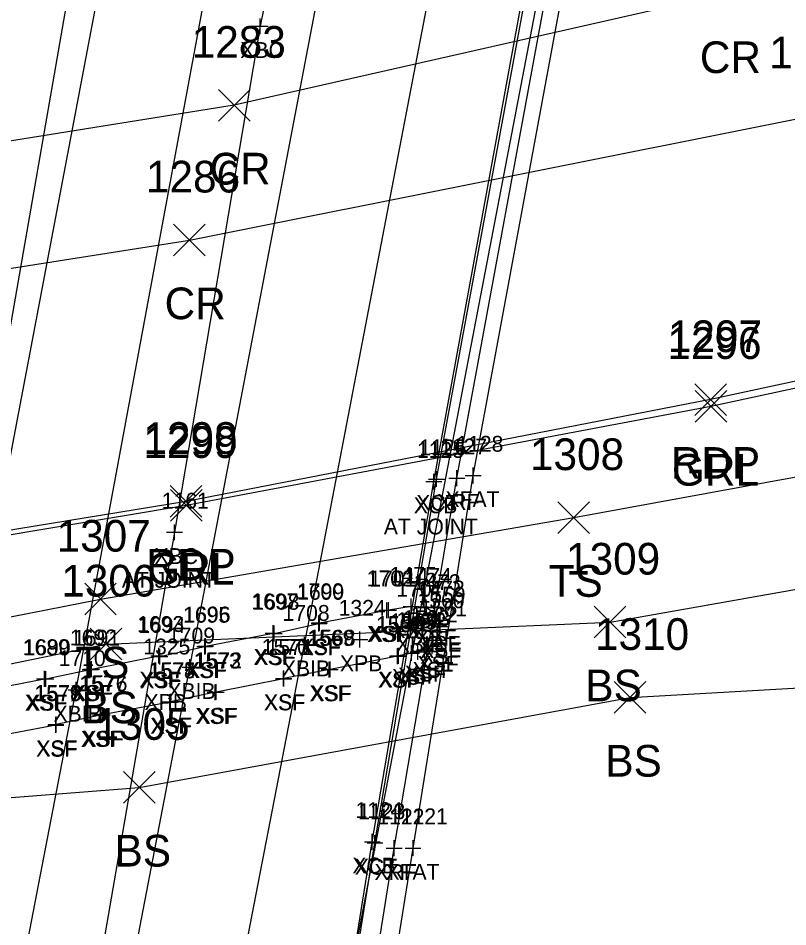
# Model space of a CAD drawing. Extents: x 1683147 to 1683637, y 416837 to 418211.
# Drawn here: x 1683231.5 to 1683280.1, y 417486.5 to 417543.9 of the extents above; entities that cross this region are included whole.
import ezdxf

# ---------------------------------------------------------------- set-up
doc = ezdxf.new("R2010")
doc.units = 0
for name, color, linetype in [('B_A', 7, 'Continuous'), ('B_C', 7, 'Continuous'), ('B_I', 7, 'Continuous'), ('B_TIC', 7, 'Continuous'), ('BB', 7, 'Continuous'), ('BDC', 7, 'Continuous'), ('BDEFAULT', 7, 'Continuous'), ('BELB', 7, 'Continuous'), ('BF', 7, 'Continuous'), ('BR', 7, 'Continuous'), ('L_A', 7, 'Continuous'), ('L_I', 7, 'Continuous'), ('L_TIC', 7, 'Continuous'), ('LELB', 7, 'Continuous'), ('P_A', 7, 'Continuous'), ('P_I', 7, 'Continuous'), ('P_TIC', 7, 'Continuous'), ('PET', 7, 'Continuous'), ('PRC', 7, 'Continuous'), ('R_A', 7, 'Continuous'), ('R_I', 7, 'Continuous'), ('R_TIC', 7, 'Continuous'), ('RGR', 7, 'Continuous')]:
    doc.layers.add(name, color=color, linetype=linetype)

msp = doc.modelspace()

# ---------------------------------------------------------------- linework, layer by layer
at = {"layer": 'B_TIC'}
for p, q in [((1683246.826, 417543.339), (1683246.901, 417543.339)), ((1683257.956, 417514.755), (1683258.031, 417514.755)), ((1683259.241, 417514.807), (1683259.316, 417514.807)), ((1683260.268, 417514.98), (1683260.344, 417514.98)), ((1683257.786, 417514.592), (1683257.862, 417514.592)), ((1683241.403, 417511.39), (1683241.478, 417511.39)), ((1683256.344, 417506.709), (1683256.42, 417506.709)), ((1683254.811, 417506.467), (1683254.886, 417506.467)), ((1683254.931, 417506.48), (1683255.006, 417506.48)), ((1683254.931, 417506.48), (1683255.006, 417506.48)), ((1683257.294, 417506.646), (1683257.369, 417506.646)), ((1683257.856, 417506.241), (1683257.931, 417506.241)), ((1683250.529, 417505.632), (1683250.604, 417505.632)), ((1683250.56, 417505.669), (1683250.636, 417505.669)), ((1683256.809, 417505.82), (1683256.885, 417505.82)), ((1683258.112, 417505.846), (1683258.187, 417505.846)), ((1683258.112, 417505.846), (1683258.187, 417505.846)), ((1683247.629, 417505.03), (1683247.705, 417505.03)), ((1683247.695, 417505.003), (1683247.771, 417505.003)), ((1683258.166, 417505.451), (1683258.241, 417505.451)), ((1683258.166, 417505.1), (1683258.242, 417505.1)), ((1683253.12, 417504.62), (1683253.195, 417504.62)), ((1683257.993, 417504.582), (1683258.068, 417504.582)), ((1683243.311, 417504.185), (1683243.386, 417504.185)), ((1683243.368, 417504.201), (1683243.443, 417504.201)), ((1683249.615, 417504.3), (1683249.691, 417504.3)), ((1683256.782, 417503.841), (1683256.858, 417503.841)), ((1683257.195, 417503.97), (1683257.271, 417503.97)), ((1683257.687, 417504.197), (1683257.762, 417504.197)), ((1683240.415, 417503.599), (1683240.491, 417503.599)), ((1683240.479, 417503.544), (1683240.555, 417503.544)), ((1683255.494, 417503.576), (1683255.57, 417503.576)), ((1683255.551, 417503.597), (1683255.626, 417503.597)), ((1683256.385, 417503.769), (1683256.46, 417503.769)), ((1683236.077, 417502.727), (1683236.152, 417502.727)), ((1683236.164, 417502.751), (1683236.239, 417502.751)), ((1683242.378, 417502.873), (1683242.454, 417502.873)), ((1683251.173, 417502.72), (1683251.248, 417502.72)), ((1683251.237, 417502.737), (1683251.312, 417502.737)), ((1683233.19, 417502.135), (1683233.266, 417502.135)), ((1683233.277, 417502.131), (1683233.352, 417502.131)), ((1683240.776, 417502.18), (1683240.851, 417502.18)), ((1683248.285, 417502.147), (1683248.361, 417502.147)), ((1683248.307, 417502.161), (1683248.382, 417502.161)), ((1683235.189, 417501.44), (1683235.264, 417501.44)), ((1683243.965, 417501.289), (1683244.041, 417501.289)), ((1683244.039, 417501.308), (1683244.115, 417501.308)), ((1683241.107, 417500.671), (1683241.182, 417500.671)), ((1683241.153, 417500.687), (1683241.229, 417500.687)), ((1683236.731, 417499.843), (1683236.806, 417499.843)), ((1683236.831, 417499.86), (1683236.907, 417499.86)), ((1683233.903, 417499.221), (1683233.978, 417499.221)), ((1683233.923, 417499.26), (1683233.998, 417499.26)), ((1683253.899, 417491.851), (1683253.975, 417491.851)), ((1683254.069, 417491.776), (1683254.144, 417491.776)), ((1683255.282, 417491.444), (1683255.357, 417491.444)), ((1683256.474, 417491.459), (1683256.549, 417491.459))]:
    msp.add_line(p, q, dxfattribs=at)
for points in [[(1683246.822, 417542.839), (1683246.822, 417543.839)], [(1683246.322, 417543.339), (1683247.322, 417543.339)], [(1683259.237, 417514.307), (1683259.237, 417515.307)], [(1683260.265, 417514.48), (1683260.265, 417515.48)], [(1683257.452, 417514.755), (1683258.452, 417514.755)], [(1683257.783, 417514.092), (1683257.783, 417515.092)], [(1683257.952, 417514.255), (1683257.952, 417515.255)], [(1683258.737, 417514.807), (1683259.737, 417514.807)], [(1683259.765, 417514.98), (1683260.765, 417514.98)], [(1683257.283, 417514.592), (1683258.283, 417514.592)], [(1683241.399, 417510.89), (1683241.399, 417511.89)], [(1683240.899, 417511.39), (1683241.899, 417511.39)], [(1683254.807, 417505.967), (1683254.807, 417506.967)], [(1683254.927, 417505.98), (1683254.927, 417506.98)], [(1683254.927, 417505.98), (1683254.927, 417506.98)], [(1683255.841, 417506.709), (1683256.841, 417506.709)], [(1683256.341, 417506.209), (1683256.341, 417507.209)], [(1683257.29, 417506.146), (1683257.29, 417507.146)], [(1683257.852, 417505.741), (1683257.852, 417506.741)], [(1683250.525, 417505.132), (1683250.525, 417506.132)], [(1683250.557, 417505.169), (1683250.557, 417506.169)], [(1683254.307, 417506.467), (1683255.307, 417506.467)], [(1683254.427, 417506.48), (1683255.427, 417506.48)], [(1683254.427, 417506.48), (1683255.427, 417506.48)], [(1683256.79, 417506.646), (1683257.79, 417506.646)], [(1683256.806, 417505.32), (1683256.806, 417506.32)], [(1683257.352, 417506.241), (1683258.352, 417506.241)], [(1683258.108, 417505.346), (1683258.108, 417506.346)], [(1683258.108, 417505.346), (1683258.108, 417506.346)], [(1683247.626, 417504.53), (1683247.626, 417505.53)], [(1683250.025, 417505.632), (1683251.025, 417505.632)], [(1683250.057, 417505.669), (1683251.057, 417505.669)], [(1683256.306, 417505.82), (1683257.306, 417505.82)], [(1683257.608, 417505.846), (1683258.608, 417505.846)], [(1683257.608, 417505.846), (1683258.608, 417505.846)], [(1683258.162, 417504.951), (1683258.162, 417505.951)], [(1683258.163, 417504.6), (1683258.163, 417505.6)], [(1683247.126, 417505.03), (1683248.126, 417505.03)], [(1683247.192, 417505.003), (1683248.192, 417505.003)], [(1683247.692, 417504.503), (1683247.692, 417505.503)], [(1683253.116, 417504.12), (1683253.116, 417505.12)], [(1683257.662, 417505.451), (1683258.662, 417505.451)], [(1683257.663, 417505.1), (1683258.663, 417505.1)], [(1683257.989, 417504.082), (1683257.989, 417505.082)], [(1683243.307, 417503.685), (1683243.307, 417504.685)], [(1683243.364, 417503.701), (1683243.364, 417504.701)], [(1683249.612, 417503.8), (1683249.612, 417504.8)], [(1683252.616, 417504.62), (1683253.616, 417504.62)], [(1683257.192, 417503.47), (1683257.192, 417504.47)], [(1683257.489, 417504.582), (1683258.489, 417504.582)], [(1683257.683, 417503.697), (1683257.683, 417504.697)], [(1683240.412, 417503.099), (1683240.412, 417504.099)], [(1683240.476, 417503.044), (1683240.476, 417504.044)], [(1683242.807, 417504.185), (1683243.807, 417504.185)], [(1683242.864, 417504.201), (1683243.864, 417504.201)], [(1683249.112, 417504.3), (1683250.112, 417504.3)], [(1683255.491, 417503.076), (1683255.491, 417504.076)], [(1683255.547, 417503.097), (1683255.547, 417504.097)], [(1683256.279, 417503.841), (1683257.279, 417503.841)], [(1683256.381, 417503.269), (1683256.381, 417504.269)], [(1683256.692, 417503.97), (1683257.692, 417503.97)], [(1683256.779, 417503.341), (1683256.779, 417504.341)], [(1683257.183, 417504.197), (1683258.183, 417504.197)], [(1683236.073, 417502.227), (1683236.073, 417503.227)], [(1683236.16, 417502.251), (1683236.16, 417503.251)], [(1683239.912, 417503.599), (1683240.912, 417503.599)], [(1683239.976, 417503.544), (1683240.976, 417503.544)], [(1683242.375, 417502.373), (1683242.375, 417503.373)], [(1683251.169, 417502.22), (1683251.169, 417503.22)], [(1683251.233, 417502.237), (1683251.233, 417503.237)], [(1683254.991, 417503.576), (1683255.991, 417503.576)], [(1683255.047, 417503.597), (1683256.047, 417503.597)], [(1683255.881, 417503.769), (1683256.881, 417503.769)], [(1683235.573, 417502.727), (1683236.573, 417502.727)], [(1683235.66, 417502.751), (1683236.66, 417502.751)], [(1683240.772, 417501.68), (1683240.772, 417502.68)], [(1683241.875, 417502.873), (1683242.875, 417502.873)], [(1683248.282, 417501.647), (1683248.282, 417502.647)], [(1683248.303, 417501.661), (1683248.303, 417502.661)], [(1683250.669, 417502.72), (1683251.669, 417502.72)], [(1683250.733, 417502.737), (1683251.733, 417502.737)], [(1683232.687, 417502.135), (1683233.687, 417502.135)], [(1683232.773, 417502.131), (1683233.773, 417502.131)], [(1683233.187, 417501.635), (1683233.187, 417502.635)], [(1683233.273, 417501.631), (1683233.273, 417502.631)], [(1683240.272, 417502.18), (1683241.272, 417502.18)], [(1683247.782, 417502.147), (1683248.782, 417502.147)], [(1683247.803, 417502.161), (1683248.803, 417502.161)], [(1683235.185, 417500.94), (1683235.185, 417501.94)], [(1683243.962, 417500.789), (1683243.962, 417501.789)], [(1683244.036, 417500.808), (1683244.036, 417501.808)], [(1683234.685, 417501.44), (1683235.685, 417501.44)], [(1683241.103, 417500.171), (1683241.103, 417501.171)], [(1683241.15, 417500.187), (1683241.15, 417501.187)], [(1683243.462, 417501.289), (1683244.462, 417501.289)], [(1683243.536, 417501.308), (1683244.536, 417501.308)], [(1683236.828, 417499.36), (1683236.828, 417500.36)], [(1683240.603, 417500.671), (1683241.603, 417500.671)], [(1683240.65, 417500.687), (1683241.65, 417500.687)], [(1683236.227, 417499.843), (1683237.227, 417499.843)], [(1683236.328, 417499.86), (1683237.328, 417499.86)], [(1683236.727, 417499.343), (1683236.727, 417500.343)], [(1683233.399, 417499.221), (1683234.399, 417499.221)], [(1683233.419, 417499.26), (1683234.419, 417499.26)], [(1683233.899, 417498.721), (1683233.899, 417499.721)], [(1683233.919, 417498.76), (1683233.919, 417499.76)], [(1683253.896, 417491.351), (1683253.896, 417492.351)], [(1683253.396, 417491.851), (1683254.396, 417491.851)], [(1683253.565, 417491.776), (1683254.565, 417491.776)], [(1683254.065, 417491.276), (1683254.065, 417492.276)], [(1683255.278, 417490.944), (1683255.278, 417491.944)], [(1683256.47, 417490.959), (1683256.47, 417491.959)], [(1683254.778, 417491.444), (1683255.778, 417491.444)], [(1683255.97, 417491.459), (1683256.97, 417491.459)]]:
    msp.add_lwpolyline(points, dxfattribs=at)
at = {"layer": 'BB'}
for points in [[(1683247.534, 417457.283), (1683256.806, 417505.82), (1683275.504, 417603.185), (1683284.507, 417651.57)], [(1683240.224, 417455.825), (1683249.612, 417504.3), (1683268.309, 417601.755), (1683277.362, 417650.167)], [(1683233.056, 417454.423), (1683242.375, 417502.873), (1683260.963, 417600.277), (1683270.09, 417648.672)], [(1683225.817, 417452.979), (1683235.185, 417501.44), (1683252.981, 417597.315), (1683262.91, 417647.271)], [(1683218.639, 417451.571), (1683227.942, 417499.995), (1683246.282, 417596.559), (1683255.565, 417645.821)]]:
    msp.add_lwpolyline(points, dxfattribs=at)
at = {"layer": 'BDC'}
for points in [[(1683248.051, 417455.436), (1683253.896, 417491.851), (1683257.783, 417514.592), (1683265.936, 417559.114), (1683272.886, 417593.685), (1683281.07, 417631.095), (1683286.315, 417653.984)], [(1683248.206, 417455.394), (1683254.065, 417491.776), (1683257.952, 417514.755), (1683266.138, 417559.151), (1683273.116, 417593.593), (1683281.173, 417630.923), (1683286.527, 417654.075)]]:
    msp.add_lwpolyline(points, dxfattribs=at)
at = {"layer": 'BDEFAULT'}
for points in [[(1683258.108, 417505.846), (1683257.852, 417506.241), (1683257.29, 417506.646), (1683256.341, 417506.709), (1683254.927, 417506.48)], [(1683228.937, 417501.313), (1683233.187, 417502.135), (1683233.273, 417502.131), (1683236.073, 417502.727), (1683236.16, 417502.751), (1683240.412, 417503.599), (1683240.476, 417503.544), (1683243.307, 417504.185), (1683243.364, 417504.201), (1683247.626, 417505.03), (1683247.692, 417505.003), (1683250.525, 417505.632), (1683250.557, 417505.669), (1683254.807, 417506.467), (1683254.927, 417506.48)], [(1683258.108, 417505.846), (1683258.162, 417505.451), (1683258.163, 417505.1), (1683257.989, 417504.582), (1683257.683, 417504.197), (1683257.192, 417503.97), (1683256.779, 417503.841), (1683256.381, 417503.769), (1683255.547, 417503.597), (1683255.491, 417503.576), (1683251.233, 417502.737), (1683251.169, 417502.72), (1683248.303, 417502.161), (1683248.282, 417502.147), (1683244.036, 417501.308), (1683243.962, 417501.289), (1683241.15, 417500.687), (1683241.103, 417500.671), (1683236.828, 417499.86), (1683236.727, 417499.843), (1683233.919, 417499.26), (1683233.899, 417499.221), (1683229.649, 417498.419)]]:
    msp.add_lwpolyline(points, dxfattribs=at)
at = {"layer": 'BELB'}
for points in [[(1683269.206, 417650.948), (1683260.393, 417611.397), (1683256.447, 417590.785), (1683246.822, 417543.339), (1683241.399, 417511.39), (1683234.932, 417474.067), (1683231.661, 417452.147)], [(1683255.821, 417648.166), (1683248.035, 417613.702), (1683243.06, 417587.805), (1683234.781, 417546.02), (1683228.274, 417508.761), (1683222.317, 417473.758), (1683218.863, 417449.537)]]:
    msp.add_lwpolyline(points, dxfattribs=at)
at = {"layer": 'BF'}
msp.add_lwpolyline([(1683250.624, 417454.9), (1683256.47, 417491.459), (1683260.265, 417514.98), (1683268.347, 417558.692), (1683275.679, 417593.916), (1683283.544, 417630.285), (1683288.924, 417653.565)], dxfattribs=at)
at = {"layer": 'BR'}
msp.add_lwpolyline([(1683248.519, 417448.641), (1683249.479, 417455.186), (1683255.278, 417491.444), (1683259.237, 417514.807), (1683267.406, 417559.099), (1683274.406, 417593.753), (1683282.508, 417630.53), (1683290.526, 417665.488)], dxfattribs=at)
at = {"layer": 'L_TIC'}
for points in [[(1683265.627, 417511.319), (1683267.627, 417513.319)], [(1683267.627, 417511.319), (1683265.627, 417513.319)], [(1683235.725, 417506.171), (1683237.725, 417508.171)], [(1683237.725, 417506.171), (1683235.725, 417508.171)], [(1683267.914, 417504.721), (1683269.914, 417506.721)], [(1683269.914, 417504.721), (1683267.914, 417506.721)], [(1683236.075, 417503.337), (1683238.075, 417505.337)], [(1683238.075, 417503.337), (1683236.075, 417505.337)], [(1683269.177, 417499.965), (1683271.177, 417501.965)], [(1683271.177, 417499.965), (1683269.177, 417501.965)], [(1683238.174, 417494.288), (1683240.174, 417496.288)], [(1683240.174, 417494.288), (1683238.174, 417496.288)]]:
    msp.add_lwpolyline(points, dxfattribs=at)
at = {"layer": 'LELB'}
for points in [[(1683205.058, 417500.966), (1683236.725, 417507.171), (1683266.627, 417512.319), (1683295.742, 417517.653), (1683322.975, 417523.071), (1683351.626, 417530.069)], [(1683205.591, 417497.875), (1683237.075, 417504.337), (1683268.914, 417505.721), (1683296.171, 417510.545), (1683323.546, 417516.347), (1683350.433, 417523.399)], [(1683205.213, 417492.626), (1683239.174, 417495.288), (1683270.177, 417500.965), (1683298.559, 417502.586), (1683327.653, 417507.076), (1683349.696, 417514.294)]]:
    msp.add_lwpolyline(points, dxfattribs=at)
at = {"layer": 'P_TIC'}
for points in [[(1683244.179, 417537.35), (1683246.179, 417539.35)], [(1683246.179, 417537.35), (1683244.179, 417539.35)], [(1683241.343, 417528.845), (1683243.343, 417530.845)], [(1683243.343, 417528.845), (1683241.343, 417530.845)], [(1683274.263, 417518.769), (1683276.263, 417520.769)], [(1683276.263, 417518.769), (1683274.263, 417520.769)], [(1683241.13, 417512.342), (1683243.13, 417514.342)], [(1683243.13, 417512.342), (1683241.13, 417514.342)]]:
    msp.add_lwpolyline(points, dxfattribs=at)
at = {"layer": 'PET'}
msp.add_lwpolyline([(1683351.521, 417537.139), (1683327.502, 417531.164), (1683310.333, 417527.312), (1683275.263, 417519.769), (1683242.13, 417513.342), (1683204.728, 417507.24)], dxfattribs=at)
at = {"layer": 'PRC'}
for points in [[(1683342.592, 417562.589), (1683311.955, 417553.502), (1683276.156, 417545.385), (1683245.179, 417538.35), (1683203.393, 417531.667)], [(1683202.452, 417523.569), (1683242.343, 417529.845), (1683281.666, 417537.682), (1683320.124, 417546.282), (1683360.503, 417556.965)]]:
    msp.add_lwpolyline(points, dxfattribs=at)
at = {"layer": 'R_TIC'}
for points in [[(1683274.284, 417518.336), (1683276.284, 417520.336)], [(1683276.284, 417518.336), (1683274.284, 417520.336)], [(1683241.138, 417512.085), (1683243.138, 417514.085)], [(1683243.138, 417512.085), (1683241.138, 417514.085)]]:
    msp.add_lwpolyline(points, dxfattribs=at)
at = {"layer": 'RGR'}
msp.add_lwpolyline([(1683351.634, 417536.475), (1683327.504, 417530.568), (1683310.27, 417526.858), (1683275.284, 417519.336), (1683242.138, 417513.085), (1683204.773, 417506.832)], dxfattribs=at)

# ---------------------------------------------------------------- texts
at = {"layer": 'B_A'}
for s, p in [('XBC', (1683245.558, 417541.339)), ('XCB', (1683256.519, 417512.592)), ('XCT', (1683256.673, 417512.755)), ('XRF', (1683257.997, 417512.807)), ('XFAT', (1683258.521, 417512.98)), ('XBC', (1683240.135, 417509.39)), ('XSF', (1683255.101, 417504.709)), ('XSF', (1683256.05, 417504.646)), ('XSF', (1683253.567, 417504.467)), ('XSF', (1683253.687, 417504.48)), ('XSF', (1683253.687, 417504.48)), ('XSF', (1683256.612, 417504.241)), ('XSF', (1683249.285, 417503.632)), ('XSF', (1683249.316, 417503.669)), ('XBIB', (1683255.377, 417503.82)), ('XSF', (1683256.868, 417503.846)), ('XSF', (1683256.868, 417503.846)), ('XSF', (1683256.922, 417503.451)), ('XSF', (1683246.386, 417503.03)), ('XSF', (1683246.452, 417503.003)), ('XSF', (1683256.922, 417503.1)), ('XSF', (1683242.124, 417502.201)), ('XBIB', (1683248.183, 417502.3)), ('XPB', (1683251.852, 417502.62)), ('XSF', (1683256.749, 417502.582)), ('XSF', (1683242.067, 417502.185)), ('XSF', (1683255.141, 417501.769)), ('XSF', (1683255.539, 417501.841)), ('XSF', (1683255.952, 417501.97)), ('XSF', (1683256.443, 417502.197)), ('XSF', (1683239.172, 417501.599)), ('XSF', (1683239.236, 417501.544)), ('XSF', (1683254.251, 417501.576)), ('XSF', (1683254.307, 417501.597)), ('XSF', (1683234.833, 417500.727)), ('XSF', (1683234.92, 417500.751)), ('XBIB', (1683240.946, 417500.873)), ('XSF', (1683249.929, 417500.72)), ('XSF', (1683249.993, 417500.737)), ('XSF', (1683231.947, 417500.135)), ('XSF', (1683232.033, 417500.131)), ('XPB', (1683239.508, 417500.18)), ('XSF', (1683247.042, 417500.147)), ('XSF', (1683247.063, 417500.161)), ('XBIB', (1683233.756, 417499.44)), ('XSF', (1683242.722, 417499.289)), ('XSF', (1683242.796, 417499.308)), ('XSF', (1683239.863, 417498.671)), ('XSF', (1683239.91, 417498.687)), ('XSF', (1683235.487, 417497.843)), ('XSF', (1683235.587, 417497.86)), ('XSF', (1683232.659, 417497.221)), ('XSF', (1683232.679, 417497.26)), ('XCB', (1683252.632, 417489.851)), ('XCT', (1683252.786, 417489.776)), ('XRF', (1683254.038, 417489.444)), ('XFAT', (1683254.726, 417489.459))]:
    msp.add_text(s, height=1, dxfattribs=at).set_placement(p)
at = {"layer": 'B_C'}
for p in [(1683254.625, 417511.255), (1683238.072, 417507.89)]:
    msp.add_text('AT JOINT', height=1, dxfattribs=at).set_placement(p)
at = {"layer": 'B_I'}
for s, p in [('1125', (1683256.72, 417516.092)), ('1126', (1683256.862, 417516.255)), ('1127', (1683258.174, 417516.307)), ('1128', (1683259.202, 417516.48)), ('1161', (1683240.596, 417512.89)), ('1702', (1683253.541, 417507.98)), ('1702', (1683253.541, 417507.98)), ('1701', (1683253.705, 417507.967)), ('1475', (1683254.994, 417508.209)), ('1474', (1683255.944, 417508.146)), ('1473', (1683256.506, 417507.741)), ('1700', (1683249.128, 417507.169)), ('1699', (1683249.151, 417507.132)), ('1707', (1683255.42, 417507.32)), ('1472', (1683256.762, 417507.346)), ('1472', (1683256.762, 417507.346)), ('1559', (1683256.812, 417506.951)), ('1697', (1683246.256, 417506.53)), ('1698', (1683246.322, 417506.503)), ('1560', (1683256.749, 417506.6)), ('1695', (1683241.937, 417505.685)), ('1696', (1683241.967, 417505.701)), ('1708', (1683248.226, 417505.8)), ('1324', (1683251.77, 417506.12)), ('1562', (1683256.313, 417505.697)), ('1561', (1683256.903, 417506.082)), ('1693', (1683239.042, 417505.099)), ('1567', (1683254.121, 417505.076)), ('1566', (1683254.15, 417505.097)), ('1565', (1683255.011, 417505.269)), ('1564', (1683255.409, 417505.341)), ('1563', (1683255.822, 417505.47)), ('1694', (1683239.106, 417505.044)), ('1692', (1683234.79, 417504.251)), ('1691', (1683234.987, 417504.227)), ('1709', (1683240.985, 417504.373)), ('1569', (1683249.795, 417504.22)), ('1568', (1683249.863, 417504.237)), ('1689', (1683231.813, 417503.635)), ('1690', (1683231.86, 417503.631)), ('1325', (1683239.426, 417503.68)), ('1570', (1683246.914, 417503.661)), ('1571', (1683247.219, 417503.647)), ('1710', (1683234.079, 417502.94)), ('1573', (1683242.615, 417502.789)), ('1572', (1683242.689, 417502.808)), ('1575', (1683239.757, 417502.171)), ('1574', (1683239.803, 417502.187)), ('1577', (1683235.381, 417501.343)), ('1576', (1683235.454, 417501.36)), ('1579', (1683232.549, 417500.721)), ('1578', (1683232.573, 417500.76)), ('1124', (1683252.833, 417493.351)), ('1123', (1683253.002, 417493.276)), ('1122', (1683254.215, 417492.944)), ('1121', (1683255.691, 417492.959))]:
    msp.add_text(s, height=1, dxfattribs=at).set_placement(p)
at = {"layer": 'L_A'}
for s, p in [('TS', (1683265.037, 417507.319)), ('TS', (1683235.135, 417502.171)), ('BS', (1683267.355, 417500.721)), ('BS', (1683235.516, 417499.337)), ('BS', (1683268.618, 417495.965)), ('BS', (1683237.615, 417490.288))]:
    msp.add_text(s, height=2, dxfattribs=at).set_placement(p)
at = {"layer": 'L_I'}
for s, p in [('1308', (1683263.856, 417515.319)), ('1307', (1683233.954, 417510.171)), ('1309', (1683266.135, 417508.721)), ('1306', (1683234.248, 417507.337)), ('1310', (1683267.965, 417503.965)), ('1305', (1683236.402, 417498.288))]:
    msp.add_text(s, height=2, dxfattribs=at).set_placement(p)
at = {"layer": 'P_A'}
for s, p in [('CR', (1683274.589, 417540.385)), ('CR', (1683243.612, 417533.35)), ('CR', (1683240.776, 417524.845)), ('RDP', (1683272.751, 417514.769)), ('RDP', (1683239.618, 417508.342))]:
    msp.add_text(s, height=2, dxfattribs=at).set_placement(p)
at = {"layer": 'P_I'}
for s, p in [('1283', (1683242.487, 417541.35)), ('1287', (1683278.973, 417540.682)), ('1286', (1683239.595, 417532.845)), ('1297', (1683272.57, 417522.769)), ('1298', (1683239.437, 417516.342))]:
    msp.add_text(s, height=2, dxfattribs=at).set_placement(p)
at = {"layer": 'R_A'}
for p in [(1683272.827, 417514.336), (1683239.681, 417508.085)]:
    msp.add_text('GRL', height=2, dxfattribs=at).set_placement(p)
at = {"layer": 'R_I'}
for s, p in [('1296', (1683272.536, 417522.336)), ('1299', (1683239.437, 417516.085))]:
    msp.add_text(s, height=2, dxfattribs=at).set_placement(p)

doc.saveas('drawing.dxf')
